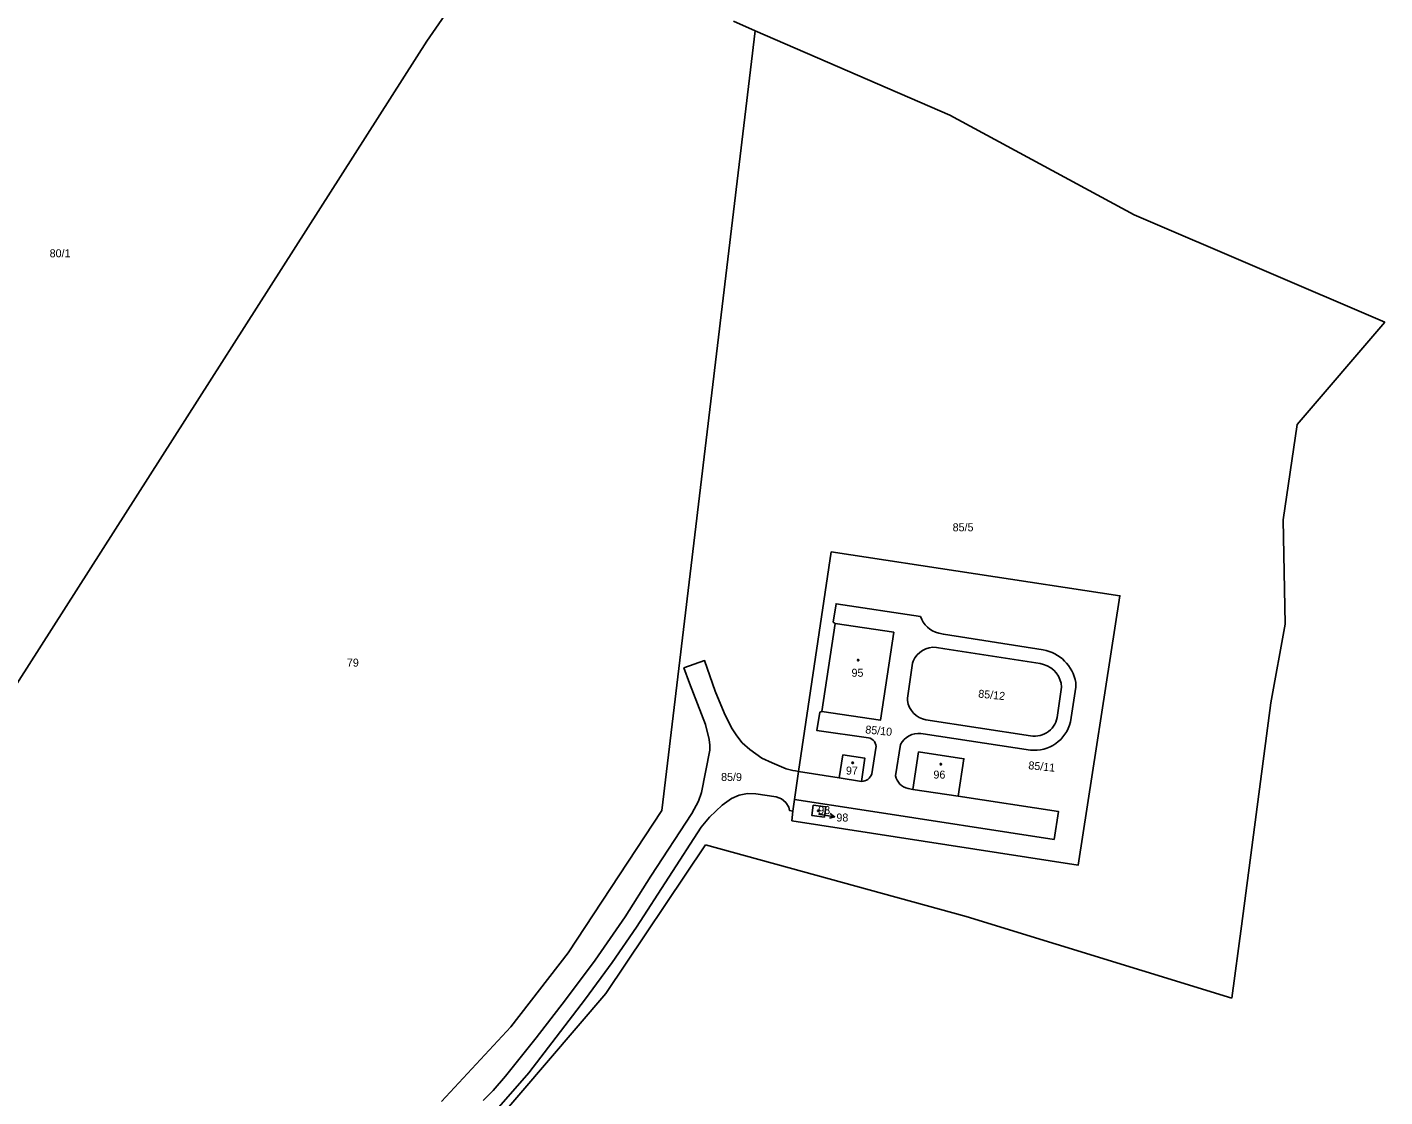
# Model space of a CAD drawing. Extents: x -752500 to -750336, y -1035826 to -1033500.
# Drawn here: x -750904.8 to -750616.5, y -1035019.2 to -1034792.1 of the extents above; entities that cross this region are included whole.
import ezdxf

# ---------------------------------------------------------------- set-up
doc = ezdxf.new("R2010")
doc.units = 0
for name, color, linetype in [('Default', 7, 'Continuous'), ('Hranice kat_území', 7, 'Continuous'), ('Hranice parcel', 7, 'Continuous'), ('Parcelní čísla', 7, 'Continuous'), ('Pop  PČ popisy', 7, 'Continuous'), ('Značky budov', 7, 'Continuous')]:
    doc.layers.add(name, color=color, linetype=linetype)

# ---------------------------------------------------------------- blocks, each defined once
blk = doc.blocks.new('10292')
at = {"layer": 'Default'}
blk.add_line((0, 3), (0, 0), dxfattribs=at)
blk.add_lwpolyline([(-0.5, 2), (0, 3), (0.5, 2)], dxfattribs=at)
blk = doc.blocks.new('402')
at = {"layer": 'Default'}
blk.add_lwpolyline([(0.09, 0.15), (0.18, 0), (0.09, -0.15), (-0.09, -0.15), (-0.18, 0), (-0.09, 0.15), (0.09, 0.15)], dxfattribs=at)

msp = doc.modelspace()

# ---------------------------------------------------------------- linework, layer by layer
at = {"layer": 'Hranice kat_území'}
for p, q in [((-750754.83, -1034790.88), (-750750.21, -1034792.89)), ((-750750.21, -1034792.89), (-750708.89, -1034810.84)), ((-750708.89, -1034810.84), (-750669.68, -1034832)), ((-750669.68, -1034832), (-750616.47, -1034854.77)), ((-750616.47, -1034854.77), (-750635.06, -1034876.44)), ((-750638.09, -1034896.73), (-750635.06, -1034876.44)), ((-750638.09, -1034896.73), (-750637.62, -1034918.84)), ((-750637.62, -1034918.84), (-750640.67, -1034935.58)), ((-750646.9, -1034982.97), (-750640.67, -1034935.58)), ((-750760.75, -1034965.71), (-750781.93, -1034997.22)), ((-750705.36, -1034980.91), (-750760.75, -1034965.71)), ((-750648.98, -1034998.22), (-750705.36, -1034980.91)), ((-750646.9, -1034982.97), (-750648.98, -1034998.22)), ((-750781.93, -1034997.22), (-750808.77, -1035028.55))]:
    msp.add_line(p, q, dxfattribs=at)
at = {"layer": 'Hranice parcel'}
for p, q in [((-750798.43, -1034763.86), (-750819.97, -1034795.13)), ((-750770.01, -1034958.43), (-750750.21, -1034792.89)), ((-750819.97, -1034795.13), (-750904.38, -1034927.42)), ((-750736.05, -1034937.36), (-750733.24, -1034918.68)), ((-750733.24, -1034918.68), (-750733.62, -1034918.42)), ((-750904.38, -1034927.42), (-750974.16, -1035035.85)), ((-750685.15, -1034932.21), (-750686.02, -1034938.16)), ((-750736.5, -1034937.5), (-750736.05, -1034937.36)), ((-750691.71, -1034942.55), (-750713.95, -1034939.17)), ((-750725.42, -1034950.63), (-750724.55, -1034945.2)), ((-750720.39, -1034951.03), (-750719.32, -1034944.37)), ((-750731.56, -1034946.57), (-750732.36, -1034951.5)), ((-750715.53, -1034945.96), (-750716.75, -1034953.93)), ((-750740.97, -1034950.11), (-750741.85, -1034956.05)), ((-750740.97, -1034950.11), (-750732.36, -1034951.5)), ((-750732.36, -1034951.5), (-750727.63, -1034952.24)), ((-750717.73, -1034953.73), (-750716.75, -1034953.93)), ((-750716.75, -1034953.93), (-750707.09, -1034955.39)), ((-750741.85, -1034956.05), (-750742.17, -1034958.57)), ((-750789.92, -1034988.62), (-750770.01, -1034958.43)), ((-750742.17, -1034958.57), (-750742.43, -1034960.56)), ((-750802.11, -1035004.29), (-750789.92, -1034988.62)), ((-750816.84, -1035020.15), (-750802.11, -1035004.29))]:
    msp.add_line(p, q, dxfattribs=at)
for points in [[(-750740.97, -1034950.11), (-750734.04, -1034903.51), (-750672.73, -1034912.81), (-750681.57, -1034970), (-750742.43, -1034960.56)], [(-750715.06, -1034917.19), (-750733.02, -1034914.51), (-750733.62, -1034918.42)], [(-750733.24, -1034918.68), (-750720.77, -1034920.56), (-750723.57, -1034939.2), (-750736.05, -1034937.36)], [(-750711.21, -1034920.76), (-750710.23, -1034920.99), (-750689.04, -1034924.29)], [(-750711.7, -1034923.78), (-750709.91, -1034924.09), (-750689.67, -1034927.21), (-750688.94, -1034927.4)], [(-750807.98, -1035019.93), (-750805.82, -1035017.82), (-750803.21, -1035014.81), (-750796.68, -1035006.65), (-750790.52, -1034998.59), (-750784.17, -1034990.17), (-750777.83, -1034980.99), (-750772.33, -1034972.32), (-750763.63, -1034959.06), (-750762.25, -1034956.42), (-750761.6, -1034954.55), (-750759.81, -1034945.62), (-750759.81, -1034944.56), (-750759.94, -1034943.36), (-750760.73, -1034940.14), (-750764.17, -1034931.4), (-750765.32, -1034928.13), (-750760.93, -1034926.58), (-750758.7, -1034933.05), (-750756.82, -1034937.65), (-750755.21, -1034940.88), (-750754.13, -1034942.57), (-750752.96, -1034944.03), (-750751.34, -1034945.44), (-750748.79, -1034947.3), (-750746.6, -1034948.31), (-750743.6, -1034949.53), (-750742.19, -1034949.94), (-750741.62, -1034950.01), (-750740.97, -1034950.11)], [(-750717.87, -1034935.08), (-750717.86, -1034934.58), (-750716.76, -1034927.15), (-750716.64, -1034926.67)], [(-750682.13, -1034931.24), (-750682.12, -1034932.24), (-750683.25, -1034939.59)], [(-750736.5, -1034937.5), (-750737.1, -1034941.42), (-750726.14, -1034942.99)], [(-750715.01, -1034942.08), (-750714.51, -1034942.11), (-750691.76, -1034945.57)], [(-750727.63, -1034952.24), (-750726.88, -1034947.32), (-750731.56, -1034946.57)], [(-750707.09, -1034955.39), (-750705.86, -1034947.4), (-750715.53, -1034945.96)], [(-750742.17, -1034958.57), (-750742.9, -1034958.43), (-750743.08, -1034957.71), (-750743.69, -1034956.69), (-750744.6, -1034955.9), (-750745.72, -1034955.47), (-750750.07, -1034954.85), (-750751.83, -1034954.8), (-750753.57, -1034955.12), (-750755.23, -1034955.85), (-750757.21, -1034957.3), (-750759.93, -1034959.79), (-750761.67, -1034961.93), (-750775.39, -1034983.18), (-750780.59, -1034990.68), (-750786.23, -1034998.38), (-750792.44, -1035006.54), (-750798.27, -1035014.08), (-750804.62, -1035021.34)], [(-750741.85, -1034956.05), (-750726.13, -1034958.47), (-750686.71, -1034964.52), (-750685.78, -1034958.62), (-750707.09, -1034955.39)]]:
    msp.add_lwpolyline(points, dxfattribs=at)
msp.add_lwpolyline([(-750737.85, -1034957.26), (-750738.18, -1034959.45), (-750735.51, -1034959.8), (-750735.22, -1034957.61)], close=True, dxfattribs=at)
for centre, radius, start, end in [((-750710.09, -1034915.69), 5.2, 196.8146, 257.5075), ((-750712.22, -1034928.55), 4.8, 83.7484, 156.9086), ((-750690.54, -1034932.7), 8.54, 9.8134, 79.8559), ((-750690.32, -1034932.39), 5.17, 1.9526, 74.5195), ((-750713, -1034934.33), 4.93, 188.7216, 258.8468), ((-750690.86, -1034937.81), 7.81, 263.3736, 346.818), ((-750690.85, -1034937.78), 4.85, 259.8036, 355.4988), ((-750715.53, -1034946.3), 4.25, 82.9278, 153.0377), ((-750726.43, -1034944.87), 1.91, 350.1542, 81.3126), ((-750727.65, -1034949.89), 2.35, 270.4839, 341.6633), ((-750717.03, -1034950.38), 3.42, 190.9375, 258.2074)]:
    msp.add_arc(centre, radius, start, end, dxfattribs=at)
at = {"layer": 'Pop  PČ popisy'}
msp.add_line((-750736.77, -1034959.14), (-750736.31, -1034959.22), dxfattribs=at)

# ---------------------------------------------------------------- block references
at = {"layer": 'Pop  PČ popisy', "rotation": -99.36149900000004}
msp.add_blockref('10292', (-750736.31, -1034959.22), dxfattribs=at)
at = {"layer": 'Značky budov'}
for p in [(-750728.32, -1034926.47), (-750729.51, -1034948.26), (-750710.76, -1034948.56), (-750736.8, -1034958.45)]:
    msp.add_blockref('402', p, dxfattribs=at)

# ---------------------------------------------------------------- texts
at = {"layer": 'Parcelní čísla'}
for s, p in [('80/1', (-750900.04, -1034840.98)), ('85/5', (-750708.26, -1034899.14)), ('79', (-750836.91, -1034927.86)), ('95', (-750729.74, -1034930.01)), ('85/9', (-750757.44, -1034952.13)), ('97', (-750730.92, -1034950.78)), ('96', (-750712.34, -1034951.63)), ('98', (-750736.81, -1034959.16)), ('98', (-750732.95, -1034960.74))]:
    msp.add_text(s, height=1.7, dxfattribs=at).set_placement(p)
for s, p in [('85/12', (-750702.88, -1034934.42)), ('85/10', (-750726.87, -1034942.02)), ('85/11', (-750692.24, -1034949.62))]:
    msp.add_text(s, height=1.7, rotation=354.317, dxfattribs=at).set_placement(p)

doc.saveas('drawing.dxf')
